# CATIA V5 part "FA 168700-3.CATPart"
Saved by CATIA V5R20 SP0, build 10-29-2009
Part number: FA 168700-3
Revision: ANY
Definition: UNKNOWN
Nomenclature: FA 168700-3
Source: Unknown
Bounding box of the stored display mesh (mm): x -3 to 3, y 0 to 4.95, z -3.464 to 3.464
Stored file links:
  C:\Users\Utente\Desktop\IO LAVORO\3D X SITO CF\CUMSA\3D files FA\FA 1687SF\FA 168700-3.CATPart

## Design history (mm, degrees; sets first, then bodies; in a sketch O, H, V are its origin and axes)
Body1 "Cortar-Extruir3" (main body)
  Solid1: solid without history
